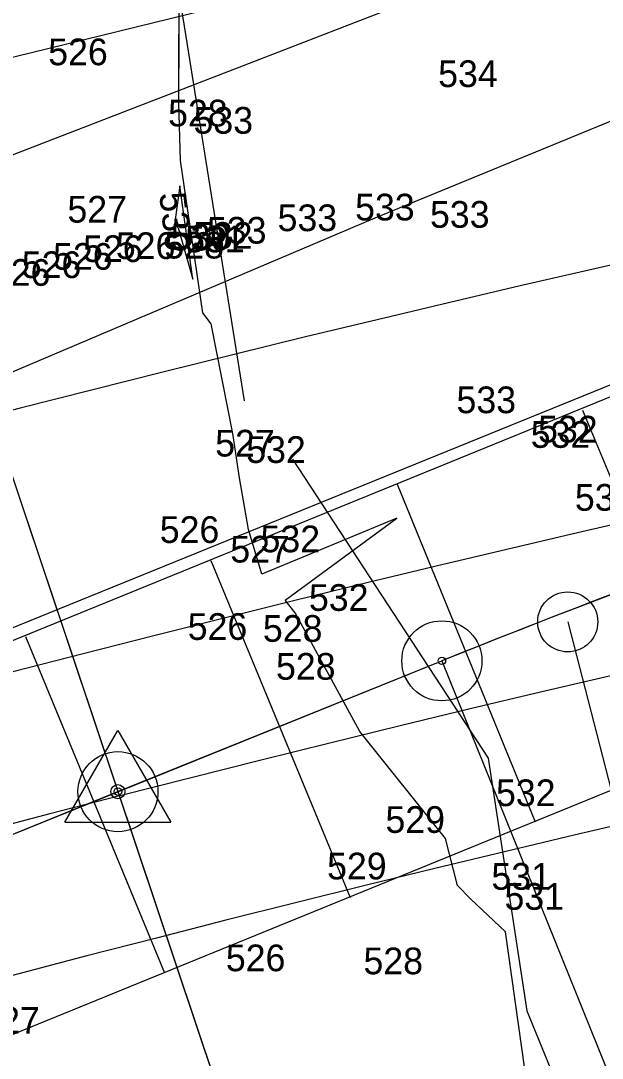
# Model space of a CAD drawing. Extents: x 1787461 to 1970323, y 938412 to 1118748.
# Drawn here: x 1967816.7 to 1967860.3, y 1117863.4 to 1117941.2 of the extents above; entities that cross this region are included whole.
import ezdxf

# ---------------------------------------------------------------- set-up
doc = ezdxf.new("R2010")
doc.units = 0
for name, color, linetype in [('Default', 7, 'Continuous'), ('HHA ADDITIONAL XSs', 7, 'Continuous'), ('Level 1', 7, 'Continuous'), ('Level 19', 7, 'Continuous'), ('RD_EX_Bridge', 7, 'Continuous'), ('RD_EX_DV_Prop', 7, 'Continuous'), ('RD_EX_H2O', 7, 'Continuous'), ('RD_EX_Misc', 7, 'Continuous'), ('RD_EX_VEG', 7, 'Continuous'), ('RD_HC_CL', 7, 'Continuous'), ('RD_HC_CL_Rel', 7, 'Continuous'), ('RD_HC_Data', 7, 'Continuous'), ('RD_PD_Final_TrvlWay', 7, 'Continuous'), ('RD_SMD_Locator', 7, 'Continuous')]:
    doc.layers.add(name, color=color, linetype=linetype)

msp = doc.modelspace()

# ---------------------------------------------------------------- linework, layer by layer
at = {"layer": 'Default'}
for points in [[(1967855.175, 1117857.477), (1967853.006, 1117872.911), (1967850.379, 1117875.392), (1967849.417, 1117876.386), (1967848.508, 1117879.908), (1967842.085, 1117887.916), (1967837.258, 1117896.828), (1967836.497, 1117897.766), (1967844.863, 1117903.915), (1967834.748, 1117899.722), (1967833.757, 1117903.052), (1967833.082, 1117906.929), (1967832.567, 1117910.262), (1967830.949, 1117918.477), (1967830.32, 1117919.294), (1967828.654, 1117930.718), (1967828.541, 1117935.041), (1967828.547, 1117945.401)], [(1967855.175, 1117857.477), (1967853.006, 1117872.911), (1967850.379, 1117875.392), (1967849.417, 1117876.386), (1967848.508, 1117879.908), (1967842.085, 1117887.916), (1967837.258, 1117896.828), (1967836.497, 1117897.766), (1967844.863, 1117903.915), (1967834.748, 1117899.722), (1967833.757, 1117903.052), (1967833.082, 1117906.929), (1967832.567, 1117910.262), (1967830.949, 1117918.477), (1967830.32, 1117919.294), (1967828.654, 1117930.718), (1967828.541, 1117935.041), (1967828.544, 1117940.198)], [(1967855.175, 1117857.477), (1967853.006, 1117872.911), (1967850.379, 1117875.392), (1967849.417, 1117876.386), (1967848.508, 1117879.908), (1967842.085, 1117887.916), (1967837.258, 1117896.828), (1967836.497, 1117897.766), (1967844.863, 1117903.915), (1967834.748, 1117899.722), (1967833.757, 1117903.052), (1967833.082, 1117906.929), (1967832.567, 1117910.262), (1967830.949, 1117918.477), (1967830.32, 1117919.294), (1967828.654, 1117930.718), (1967828.541, 1117935.041), (1967828.544, 1117940.198)], [(1967855.175, 1117857.477), (1967853.006, 1117872.911), (1967850.379, 1117875.392), (1967849.417, 1117876.386), (1967848.508, 1117879.908), (1967842.085, 1117887.916), (1967837.258, 1117896.828), (1967836.497, 1117897.766), (1967844.863, 1117903.915), (1967834.748, 1117899.722), (1967833.757, 1117903.052), (1967833.082, 1117906.929), (1967832.567, 1117910.262), (1967830.949, 1117918.477), (1967830.32, 1117919.294), (1967828.654, 1117930.718), (1967828.541, 1117935.041), (1967828.544, 1117940.198)], [(1967855.175, 1117857.477), (1967853.006, 1117872.911), (1967850.379, 1117875.392), (1967849.417, 1117876.386), (1967848.508, 1117879.908), (1967842.085, 1117887.916), (1967837.258, 1117896.828), (1967836.497, 1117897.766), (1967844.863, 1117903.915), (1967834.748, 1117899.722), (1967833.757, 1117903.052), (1967833.082, 1117906.929), (1967832.567, 1117910.262), (1967830.949, 1117918.477), (1967830.32, 1117919.294), (1967828.654, 1117930.718), (1967828.541, 1117935.041), (1967828.544, 1117940.198)], [(1967855.175, 1117857.477), (1967853.006, 1117872.911), (1967850.379, 1117875.392), (1967849.417, 1117876.386), (1967848.508, 1117879.908), (1967842.085, 1117887.916), (1967837.258, 1117896.828), (1967836.497, 1117897.766), (1967844.863, 1117903.915), (1967834.748, 1117899.722), (1967833.757, 1117903.052), (1967833.082, 1117906.929), (1967832.567, 1117910.262), (1967830.949, 1117918.477), (1967830.32, 1117919.294), (1967828.654, 1117930.718), (1967828.541, 1117935.041), (1967828.544, 1117940.198)], [(1967855.175, 1117857.477), (1967853.006, 1117872.911), (1967850.379, 1117875.392), (1967849.417, 1117876.386), (1967848.508, 1117879.908), (1967842.085, 1117887.916), (1967837.258, 1117896.828), (1967836.497, 1117897.766), (1967844.863, 1117903.915), (1967834.748, 1117899.722), (1967833.757, 1117903.052), (1967833.082, 1117906.929), (1967832.567, 1117910.262), (1967830.949, 1117918.477), (1967830.32, 1117919.294), (1967828.654, 1117930.718), (1967828.541, 1117935.041), (1967828.544, 1117940.198)], [(1967829.591, 1117921.82), (1967828.595, 1117928.832), (1967828.215, 1117925.933), (1967828.47, 1117925.68), (1967829.591, 1117921.82)], [(1967829.591, 1117921.82), (1967828.595, 1117928.832), (1967828.581, 1117928.723)], [(1967829.591, 1117921.82), (1967828.595, 1117928.832), (1967828.581, 1117928.723)], [(1967829.591, 1117921.82), (1967828.595, 1117928.832), (1967828.581, 1117928.723)], [(1967829.591, 1117921.82), (1967828.595, 1117928.832), (1967828.581, 1117928.723)], [(1967829.591, 1117921.82), (1967828.595, 1117928.832), (1967828.581, 1117928.723)], [(1967829.591, 1117921.82), (1967828.595, 1117928.832), (1967828.581, 1117928.723)], [(1967829.258, 1117922.965), (1967829.591, 1117921.82)], [(1967829.258, 1117922.965), (1967829.591, 1117921.82)], [(1967829.258, 1117922.965), (1967829.591, 1117921.82)], [(1967829.258, 1117922.965), (1967829.591, 1117921.82)], [(1967829.258, 1117922.965), (1967829.591, 1117921.82)], [(1967829.258, 1117922.965), (1967829.591, 1117921.82)]]:
    msp.add_lwpolyline(points, dxfattribs=at)
at = {"layer": 'HHA ADDITIONAL XSs'}
msp.add_lwpolyline([(1969266.553, 1117963.61), (1967907.562, 1117966.547), (1967403.979, 1117771.662), (1967075.571, 1117641.843)], dxfattribs=at)
for radius in [1667.022, 1607.022]:
    msp.add_arc((1968231.344, 1116297.536), radius, 87.726628, 111.995838, dxfattribs=at)
at = {"layer": 'Level 1'}
msp.add_lwpolyline([(1968647.287, 1117975.817), (1967967.922, 1117975.817), (1967727.472, 1117916.626), (1966985.132, 1117603.012)], dxfattribs=at)
at = {"layer": 'Level 19'}
msp.add_line((1967857.67, 1117896.136), (1967864.643, 1117869.018), dxfattribs=at)
msp.add_circle((1967857.67, 1117896.136), 2.25, dxfattribs=at)
at = {"layer": 'RD_EX_Bridge'}
msp.add_lwpolyline([(1967691.931, 1117844.089), (1967872.418, 1117917.737), (1967882.757, 1117892.409), (1967702.27, 1117818.76), (1967691.931, 1117844.089)], dxfattribs=at)
at = {"layer": 'RD_EX_DV_Prop'}
for p, q in [((1967803.582, 1117944.231), (1967823.966, 1117883.413)), ((1967823.966, 1117883.413), (1967848.241, 1117893.219)), ((1967696.84, 1117832.062), (1967823.966, 1117883.413)), ((1967823.966, 1117883.413), (1967848.586, 1117809.959))]:
    msp.add_line(p, q, dxfattribs=at)
msp.add_arc((1968093.163, 1117286.891), 653.927, 109.21172, 111.995834, dxfattribs=at)
at = {"layer": 'RD_EX_H2O'}
for points in [[(1967851.176, 1118399.396), (1967910.983, 1118393.003), (1967923.848, 1118346.179), (1967942.912, 1118303.757), (1967945.438, 1118252.513), (1967960.352, 1118200.637), (1967921.613, 1118157.979), (1967878.954, 1118126.471), (1967857.488, 1118083.002), (1967842.733, 1118040.05), (1967828.537, 1117994.006), (1967828.404, 1117944.087), (1967833.425, 1117912.714)], [(1967837.052, 1117908.322), (1967851.703, 1117885.917), (1967854.606, 1117866.99), (1967867.872, 1117834.544)]]:
    msp.add_lwpolyline(points, dxfattribs=at)
at = {"layer": 'RD_EX_Misc'}
for p, q in [((1967691.117, 1117844.933), (1967873.24, 1117918.941)), ((1967858.768, 1117912.008), (1967869.264, 1117886.806)), ((1967844.882, 1117906.454), (1967855.233, 1117881.16)), ((1967830.932, 1117900.747), (1967841.371, 1117875.479)), ((1967817.05, 1117895.043), (1967827.46, 1117869.831))]:
    msp.add_line(p, q, dxfattribs=at)
at = {"layer": 'RD_EX_VEG'}
msp.add_lwpolyline([(1967420.801, 1117819.076), (1967452.151, 1117758.283), (1967558.571, 1117805.529), (1967843.242, 1117926.429), (1967916.628, 1117956.613), (1968008.442, 1117968.2), (1968060.252, 1117967.439), (1968104.576, 1117972.693), (1968157.629, 1117966.15), (1968211.146, 1117963.438), (1968421.934, 1117955.987), (1968535.191, 1117951.616)], dxfattribs=at)
at = {"layer": 'RD_HC_CL'}
for p, q in [((1967803.582, 1117944.231), (1967848.586, 1117809.958)), ((1966769.512, 1117457.475), (1967848.241, 1117893.219))]:
    msp.add_line(p, q, dxfattribs=at)
msp.add_arc((1968093.163, 1117286.891), 653.927, 87.726628, 111.995838, dxfattribs=at)
at = {"layer": 'RD_HC_CL_Rel'}
msp.add_arc((1968231.344, 1116297.536), 1637.022, 87.726628, 111.995838, dxfattribs=at)
at = {"layer": 'RD_HC_Data'}
for p, q in [((1967848.241, 1117893.219), (1967891.709, 1117785.612)), ((1967819.995, 1117881.12), (1967823.967, 1117888)), ((1967823.967, 1117888), (1967827.936, 1117881.12)), ((1967819.995, 1117881.12), (1967827.936, 1117881.12))]:
    msp.add_line(p, q, dxfattribs=at)
for centre, radius in [((1967848.241, 1117893.219), 3), ((1967848.241, 1117893.219), 0.282), ((1967823.966, 1117883.413), 3), ((1967823.966, 1117883.413), 0.529), ((1967823.966, 1117883.413), 0.282)]:
    msp.add_circle(centre, radius, dxfattribs=at)
at = {"layer": 'RD_PD_Final_TrvlWay'}
for radius in [1648.022, 1626.022]:
    msp.add_arc((1968231.344, 1116297.536), radius, 87.726628, 111.995838, dxfattribs=at)
at = {"layer": 'RD_SMD_Locator'}
for centre in [(1967848.241, 1117893.219), (1967823.966, 1117883.413), (1967823.966, 1117883.413)]:
    msp.add_circle(centre, 0.001, dxfattribs=at)

# ---------------------------------------------------------------- texts
at = {"layer": 'Default'}
for s, p in [('526', (1967818.744, 1117937.86)), ('534', (1967847.962, 1117936.225)), ('528', (1967827.728, 1117933.274)), ('533', (1967829.632, 1117932.728)), ('527', (1967820.183, 1117926.064)), ('533', (1967841.74, 1117926.226)), ('533', (1967835.93, 1117925.424)), ('533', (1967847.35, 1117925.681)), ('533', (1967830.639, 1117924.488)), ('530', (1967827.919, 1117923.968)), ('531', (1967828.998, 1117923.838)), ('532', (1967829.593, 1117924.099)), ('526', (1967821.354, 1117923.112)), ('526', (1967823.813, 1117923.334)), ('528', (1967827.45, 1117923.373)), ('526', (1967819.104, 1117922.531)), ('526', (1967816.761, 1117921.909)), ('526', (1967814.449, 1117921.327)), ('533', (1967849.335, 1117911.781)), ('532', (1967854.898, 1117909.184)), ('532', (1967855.448, 1117909.582)), ('527', (1967831.256, 1117908.532)), ('532', (1967833.581, 1117908.052)), ('533', (1967858.207, 1117904.469)), ('526', (1967827.101, 1117902.054)), ('532', (1967834.653, 1117901.356)), ('527', (1967832.388, 1117900.587)), ('532', (1967838.28, 1117896.964)), ('526', (1967829.194, 1117894.789)), ('528', (1967834.829, 1117894.645)), ('528', (1967835.811, 1117891.803)), ('532', (1967852.294, 1117882.33)), ('529', (1967844.012, 1117880.323)), ('529', (1967839.64, 1117876.838)), ('531', (1967851.95, 1117876.06)), ('531', (1967852.931, 1117874.559)), ('526', (1967832.054, 1117869.954)), ('528', (1967842.368, 1117869.727)), ('527', (1967813.655, 1117865.275))]:
    msp.add_text(s, height=2, dxfattribs=at).set_placement(p)
msp.add_text('530', height=2, rotation=276.70827, dxfattribs=at).set_placement((1967827.053, 1117928.242))
msp.add_text('530', height=2, rotation=276.70827, dxfattribs=at).set_placement((1967827.053, 1117928.242))
msp.add_text('530', height=2, rotation=276.70827, dxfattribs=at).set_placement((1967827.053, 1117928.242))
msp.add_text('530', height=2, rotation=276.70827, dxfattribs=at).set_placement((1967827.053, 1117928.242))
msp.add_text('530', height=2, rotation=276.70827, dxfattribs=at).set_placement((1967827.053, 1117928.242))
msp.add_text('530', height=2, rotation=276.70827, dxfattribs=at).set_placement((1967827.053, 1117928.242))

doc.saveas('drawing.dxf')
